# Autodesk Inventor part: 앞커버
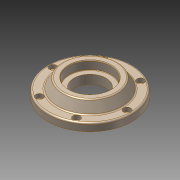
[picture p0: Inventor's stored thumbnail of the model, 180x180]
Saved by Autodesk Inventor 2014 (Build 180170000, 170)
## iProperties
Created: 2013-01
Part Number: 앞커버
Document SubType Name: Modeling
Designer: 한국산업디자인학원[gmhk.co.kr]
Density: 2.71 g/cm^3
Material: 알루미늄 6061
Mass: 321.536 g
Surface Area: 281.944 cm^2
Volume: 118.648 cm^3
Appearance: 알루미늄 - 평지(2)
Author: 한국산업디자인학원[gmhk.co.kr]
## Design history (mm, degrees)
sketch "스케치2"
  geometry: L1 (-55, 0)-(55, 0) reference; L2 (35.98, -6)-(-35.98, -6) reference; L3 (-42.5, -25)-(-42.5, 0) reference; L4 (-37, -6)-(-37, 0); L5 (-55, 0)-(-55, 10); L6 (-55, 10)-(-42.5, 10); L7 (-37, -6)-(-42.5, -6); L8 (-42.5, 10)-(-34.994, 23); L9 (-34.994, 23)-(0, 23); L10 (-55, 0)-(-42.5, 0); L11 (-42.5, -6)-(-42.5, 0); L12 (0, 0)-(0, 23); L13 (0, 0)-(-37, 0)
  constraints: 22 end point, 4 perpendicular, 3 collinear, 2 parallel, 2 point on line, 1 vertical, 2 other
  dimensions: "d2" = 10 distance of L1.start L5.end; "d4" = 120 deg angle of L8 L6; "d5" = 13 distance between parallel lines of L6 L9; "d6" = 74 diameter of L4 L12; "d7" = 85 diameter of L6.end L12
revolve "회전1" sketch "스케치2" stored, may be unused: angle "d8" = 90 deg
fillet "모깎기1" dims "d9" = 2
sketch "스케치3"
  geometry: C1 r 2.067 at (48.5, 0) reference; 1 further point
hole "구멍1" sketch "스케치3" at (48.5, 0) diameter "d10" = 5.5; stored, may be unused: countersink angle "d14" = 90 deg, drill point angle "d16" = 118 deg; dims "d11" = 6, "d12" = 9.5, "d13" = 5.4, "d15" = 8
fillet "모깎기2" dims "d20" = 3
chamfer "모따기1" distance "d21" = 1; stored, may be unused: second distance "d22" = 2, angle "d23" = 45 deg
sketch "스케치4"
  geometry: L1 (-33.84, 23)-(33.84, 23) reference; L2 (34, 0)-(-34, 0) reference; L3 (0, 0)-(0, 23); L4 (27.5, 21.9)-(27.5, 12.1); L5 (27, 11.6)-(21, 11.6); L6 (21, 11.6)-(21, 0); L7 (27.5, 21.9)-(28.135, 23); A1 r 0.5 centre (27, 12.1) between (27, 11.6) and (27.5, 12.1)
  constraints: 10 end point, 2 perpendicular, 2 point on circle, 2 point on line, 2 tangent, 1 centre point, 1 midpoint, 1 parallel
  dimensions: "d24" = 11.4 distance between parallel lines of L5 L1; "d25" = 1.1 distance from line of L4.start L1; "d26" = 30 deg angle of L7 L4; "d27" = 0.5 radius of A1; "d28" = 55 diameter of L4 L3; "d29" = 42 diameter of L6 L3
revolve "회전2" sketch "스케치4" stored, may be unused: angle "d30" = 90 deg
node "솔리드1"
pattern_circular "원형 패턴1" dims angle "d18" = 360 deg
node "참조1"
node "참조2"
node "참조3"
